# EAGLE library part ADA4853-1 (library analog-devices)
Low Power, Rail-to-Rail Output, Video Op Amps with Ultralow Power Source: http://www.analog.com/static/imported-files/data_sheets/ADA4853-1_4853-2_4853-3.pdf
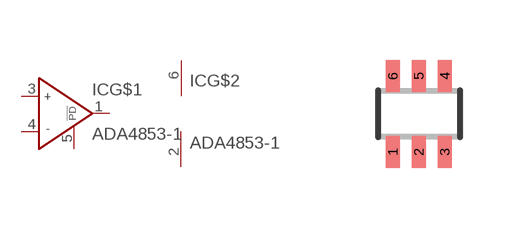
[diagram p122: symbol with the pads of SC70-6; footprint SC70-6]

Designator prefix IC; gates G$1=OP_PD G$2=PWR+-

## ADA4853-1 (OC_FARNELL: unknown; OC_NEWARK: unknown)  [SC70-6]
1  G$1:OUT  out
2  G$2:V-  pwr
3  G$1:IN+  in
4  G$1:IN-  in
5  G$1:!POWERDOWN  pas
6  G$2:V+  pwr

## Footprint SC70-6 (pad centres in mm)
6-Lead Thin Shrink Small Outline Transistor Package SC70 Source: http://www.analog.com/static/imported-files/data_sheets/ADA4853-1_4853-2_4853-3.pdf
smd 0.35 x 0.8: 1 -0.65,-0.95; 2 0,-0.95; 3 0.65,-0.95; 4 0.65,0.95; 5 0,0.95; 6 -0.65,0.95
